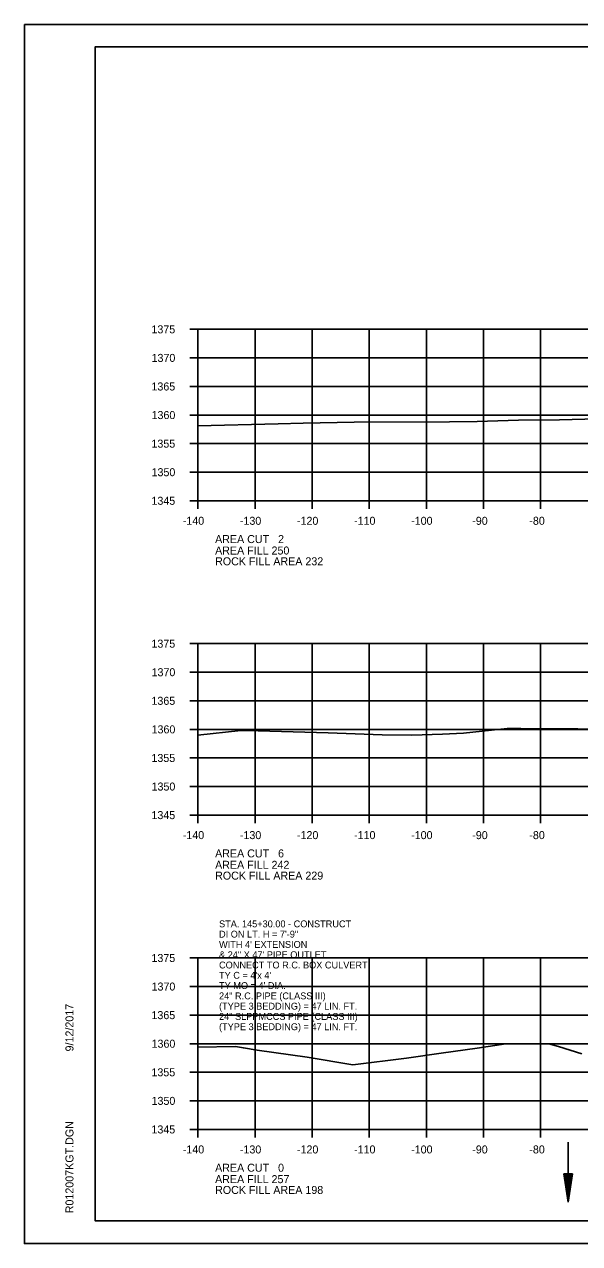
# Model space of a CAD drawing. Extents: x 1374311 to 1383814, y 384102 to 406278.
# Drawn here: x 1381458.2 to 1381555.5, y 390511.4 to 390724.7 of the extents above; entities that cross this region are included whole.
import ezdxf

# ---------------------------------------------------------------- set-up
doc = ezdxf.new("R2010")
doc.units = 0
for name, color, linetype in [('R_Axis', 7, 'Continuous'), ('R_Axis Annot', 7, 'Continuous'), ('R_Border', 7, 'Continuous'), ('R_Draft', 7, 'Continuous'), ('R_Exist Surface', 7, 'Continuous'), ('R_Grid', 7, 'Continuous'), ('R_No Plot', 7, 'Continuous'), ('R_Water', 7, 'Continuous'), ('R_Water Annot', 7, 'Continuous')]:
    doc.layers.add(name, color=color, linetype=linetype)

msp = doc.modelspace()

# ---------------------------------------------------------------- linework, layer by layer
at = {"layer": 'R_Axis'}
for p, q in [((1381487.26, 390671.38), (1381488.66, 390671.38)), ((1381488.66, 390641.38), (1381488.66, 390671.38)), ((1381487.26, 390666.38), (1381488.66, 390666.38)), ((1381487.26, 390661.38), (1381488.66, 390661.38)), ((1381487.26, 390656.38), (1381488.66, 390656.38)), ((1381487.26, 390651.38), (1381488.66, 390651.38)), ((1381487.26, 390646.38), (1381488.66, 390646.38)), ((1381487.26, 390641.38), (1381488.66, 390641.38)), ((1381488.66, 390641.38), (1381768.66, 390641.38)), ((1381488.66, 390639.98), (1381488.66, 390641.38)), ((1381498.66, 390639.98), (1381498.66, 390641.38)), ((1381508.66, 390639.98), (1381508.66, 390641.38)), ((1381518.66, 390639.98), (1381518.66, 390641.38)), ((1381528.66, 390639.98), (1381528.66, 390641.38)), ((1381538.66, 390639.98), (1381538.66, 390641.38)), ((1381548.66, 390639.98), (1381548.66, 390641.38)), ((1381487.26, 390616.38), (1381488.66, 390616.38)), ((1381488.66, 390586.38), (1381488.66, 390616.38)), ((1381487.26, 390611.38), (1381488.66, 390611.38)), ((1381487.26, 390606.38), (1381488.66, 390606.38)), ((1381487.26, 390601.38), (1381488.66, 390601.38)), ((1381487.26, 390596.38), (1381488.66, 390596.38)), ((1381487.26, 390591.38), (1381488.66, 390591.38)), ((1381487.26, 390586.38), (1381488.66, 390586.38)), ((1381488.66, 390586.38), (1381768.66, 390586.38)), ((1381488.66, 390584.98), (1381488.66, 390586.38)), ((1381498.66, 390584.98), (1381498.66, 390586.38)), ((1381508.66, 390584.98), (1381508.66, 390586.38)), ((1381518.66, 390584.98), (1381518.66, 390586.38)), ((1381528.66, 390584.98), (1381528.66, 390586.38)), ((1381538.66, 390584.98), (1381538.66, 390586.38)), ((1381548.66, 390584.98), (1381548.66, 390586.38)), ((1381487.26, 390561.38), (1381488.66, 390561.38)), ((1381488.66, 390531.38), (1381488.66, 390561.38)), ((1381487.26, 390556.38), (1381488.66, 390556.38)), ((1381487.26, 390551.38), (1381488.66, 390551.38)), ((1381487.26, 390546.38), (1381488.66, 390546.38)), ((1381487.26, 390541.38), (1381488.66, 390541.38)), ((1381487.26, 390536.38), (1381488.66, 390536.38)), ((1381487.26, 390531.38), (1381488.66, 390531.38)), ((1381488.66, 390531.38), (1381768.66, 390531.38)), ((1381488.66, 390529.98), (1381488.66, 390531.38)), ((1381498.66, 390529.98), (1381498.66, 390531.38)), ((1381508.66, 390529.98), (1381508.66, 390531.38)), ((1381518.66, 390529.98), (1381518.66, 390531.38)), ((1381528.66, 390529.98), (1381528.66, 390531.38)), ((1381538.66, 390529.98), (1381538.66, 390531.38)), ((1381548.66, 390529.98), (1381548.66, 390531.38))]:
    msp.add_line(p, q, dxfattribs=at)
at = {"layer": 'R_Border'}
for p, q in [((1381470.66, 390720.84), (1381786.84, 390720.84)), ((1381470.66, 390515.38), (1381470.66, 390720.84)), ((1381470.66, 390515.38), (1381470.66, 390515.38)), ((1381786.84, 390515.38), (1381470.66, 390515.38))]:
    msp.add_line(p, q, dxfattribs=at)
at = {"layer": 'R_Draft'}
for p, q in [((1381552.74, 390523.63), (1381553.49, 390518.63)), ((1381554.24, 390523.63), (1381552.74, 390523.63)), ((1381552.87, 390523.63), (1381553.49, 390519.46)), ((1381552.99, 390523.63), (1381553.49, 390520.32)), ((1381553.12, 390523.63), (1381553.49, 390521.16)), ((1381553.25, 390523.63), (1381553.49, 390522)), ((1381553.37, 390523.63), (1381553.49, 390522.84)), ((1381554.24, 390523.63), (1381553.49, 390518.63)), ((1381553.73, 390523.63), (1381553.49, 390522)), ((1381553.99, 390523.63), (1381553.49, 390520.32)), ((1381554.12, 390523.63), (1381553.49, 390519.46)), ((1381553.86, 390523.63), (1381553.49, 390521.16)), ((1381553.61, 390523.63), (1381553.49, 390522.84))]:
    msp.add_line(p, q, dxfattribs=at)
at = {"layer": 'R_Exist Surface'}
for points in [[(1381488.66, 390654.51), (1381502.71, 390654.87), (1381507.06, 390654.97), (1381516.04, 390655.11), (1381532.71, 390655.2), (1381537.54, 390655.26), (1381544.82, 390655.48), (1381552.01, 390655.57), (1381563.05, 390655.85)], [(1381488.66, 390600.35), (1381496.16, 390601.18), (1381496.76, 390601.17), (1381497.17, 390601.16), (1381511.45, 390600.79), (1381520.94, 390600.45), (1381526.11, 390600.38), (1381531.46, 390600.54), (1381535.16, 390600.72), (1381541.71, 390601.42), (1381542.79, 390601.53), (1381543, 390601.53), (1381543.22, 390601.53), (1381545.2, 390601.53), (1381565.23, 390601.44)], [(1381488.66, 390545.75), (1381495.22, 390545.88), (1381496.63, 390545.64), (1381499.05, 390545.27), (1381507.77, 390544.02), (1381515.76, 390542.71), (1381525.17, 390543.84), (1381531.26, 390544.71), (1381537.58, 390545.61), (1381542.57, 390546.33), (1381550.11, 390546.37), (1381551.78, 390545.92), (1381555.87, 390544.61)]]:
    msp.add_lwpolyline(points, dxfattribs=at)
at = {"layer": 'R_Grid'}
for p, q in [((1381488.66, 390671.38), (1381768.66, 390671.38)), ((1381488.66, 390641.38), (1381488.66, 390671.38)), ((1381498.66, 390641.38), (1381498.66, 390671.38)), ((1381508.66, 390641.38), (1381508.66, 390671.38)), ((1381518.66, 390641.38), (1381518.66, 390671.38)), ((1381528.66, 390641.38), (1381528.66, 390671.38)), ((1381538.66, 390641.38), (1381538.66, 390671.38)), ((1381548.66, 390641.38), (1381548.66, 390671.38)), ((1381488.66, 390666.38), (1381768.66, 390666.38)), ((1381488.66, 390661.38), (1381768.66, 390661.38)), ((1381488.66, 390656.38), (1381768.66, 390656.38)), ((1381488.66, 390651.38), (1381768.66, 390651.38)), ((1381488.66, 390646.38), (1381768.66, 390646.38)), ((1381488.66, 390641.38), (1381768.66, 390641.38)), ((1381488.66, 390616.38), (1381768.66, 390616.38)), ((1381488.66, 390586.38), (1381488.66, 390616.38)), ((1381498.66, 390586.38), (1381498.66, 390616.38)), ((1381508.66, 390586.38), (1381508.66, 390616.38)), ((1381518.66, 390586.38), (1381518.66, 390616.38)), ((1381528.66, 390586.38), (1381528.66, 390616.38)), ((1381538.66, 390586.38), (1381538.66, 390616.38)), ((1381548.66, 390586.38), (1381548.66, 390616.38)), ((1381488.66, 390611.38), (1381768.66, 390611.38)), ((1381488.66, 390606.38), (1381768.66, 390606.38)), ((1381488.66, 390601.38), (1381768.66, 390601.38)), ((1381488.66, 390596.38), (1381768.66, 390596.38)), ((1381488.66, 390591.38), (1381768.66, 390591.38)), ((1381488.66, 390586.38), (1381768.66, 390586.38)), ((1381488.66, 390561.38), (1381768.66, 390561.38)), ((1381488.66, 390531.38), (1381488.66, 390561.38)), ((1381498.66, 390531.38), (1381498.66, 390561.38)), ((1381508.66, 390531.38), (1381508.66, 390561.38)), ((1381518.66, 390531.38), (1381518.66, 390561.38)), ((1381528.66, 390531.38), (1381528.66, 390561.38)), ((1381538.66, 390531.38), (1381538.66, 390561.38)), ((1381548.66, 390531.38), (1381548.66, 390561.38)), ((1381488.66, 390556.38), (1381768.66, 390556.38)), ((1381488.66, 390551.38), (1381768.66, 390551.38)), ((1381488.66, 390546.38), (1381768.66, 390546.38)), ((1381488.66, 390541.38), (1381768.66, 390541.38)), ((1381488.66, 390536.38), (1381768.66, 390536.38)), ((1381488.66, 390531.38), (1381768.66, 390531.38))]:
    msp.add_line(p, q, dxfattribs=at)
at = {"layer": 'R_No Plot'}
for p, q in [((1381458.26, 390724.74), (1381791.59, 390724.74)), ((1381458.26, 390511.41), (1381791.59, 390511.41))]:
    msp.add_line(p, q, dxfattribs=at)
for points in [[(1381458.25, 390724.74), (1381791.59, 390724.74), (1381791.59, 390511.4), (1381458.25, 390511.4)], [(1381704.58, 390720.84), (1381704.58, 390710.96), (1381740.31, 390710.96), (1381740.31, 390708.04), (1381763.51, 390708.04), (1381763.51, 390684.83), (1381786.84, 390684.83), (1381786.84, 390515.38), (1381470.66, 390515.38), (1381470.66, 390720.84)]]:
    msp.add_lwpolyline(points, close=True, dxfattribs=at)
at = {"layer": 'R_Water'}
msp.add_line((1381553.49, 390529.13), (1381553.49, 390518.63), dxfattribs=at)

# ---------------------------------------------------------------- texts
at = {"layer": 'R_Axis Annot'}
for s, p in [('1375', (1381480.51, 390670.68)), ('1370', (1381480.53, 390665.68)), ('1365', (1381480.51, 390660.68)), ('1360', (1381480.53, 390655.68)), ('1355', (1381480.51, 390650.68)), ('1350', (1381480.53, 390645.68)), ('1345', (1381480.51, 390640.68)), ('-140', (1381486, 390637.18)), ('-130', (1381496, 390637.18)), ('-120', (1381506, 390637.18)), ('-110', (1381516, 390637.18)), ('-100', (1381526, 390637.18)), ('-90', (1381536.7, 390637.18)), ('-80', (1381546.7, 390637.18)), ('AREA CUT   2', (1381491.66, 390633.98)), ('AREA FILL 250', (1381491.66, 390631.98)), ('ROCK FILL AREA 232', (1381491.66, 390630.09)), ('1375', (1381480.51, 390615.68)), ('1370', (1381480.53, 390610.68)), ('1365', (1381480.51, 390605.68)), ('1360', (1381480.53, 390600.68)), ('1355', (1381480.51, 390595.68)), ('1350', (1381480.53, 390590.68)), ('1345', (1381480.51, 390585.68)), ('-140', (1381486, 390582.18)), ('-130', (1381496, 390582.18)), ('-120', (1381506, 390582.18)), ('-110', (1381516, 390582.18)), ('-100', (1381526, 390582.18)), ('-90', (1381536.7, 390582.18)), ('-80', (1381546.7, 390582.18)), ('AREA CUT   6', (1381491.66, 390578.98)), ('AREA FILL 242', (1381491.66, 390576.98)), ('ROCK FILL AREA 229', (1381491.66, 390575.09)), ('1375', (1381480.51, 390560.68)), ('1370', (1381480.53, 390555.68)), ('1365', (1381480.51, 390550.68)), ('1360', (1381480.53, 390545.68)), ('1355', (1381480.51, 390540.68)), ('1350', (1381480.53, 390535.68)), ('1345', (1381480.51, 390530.68)), ('-140', (1381486, 390527.18)), ('-130', (1381496, 390527.18)), ('-120', (1381506, 390527.18)), ('-110', (1381516, 390527.18)), ('-100', (1381526, 390527.18)), ('-90', (1381536.7, 390527.18)), ('-80', (1381546.7, 390527.18)), ('AREA CUT   0', (1381491.66, 390523.98)), ('AREA FILL 257', (1381491.66, 390521.98)), ('ROCK FILL AREA 198', (1381491.66, 390520.09))]:
    msp.add_text(s, height=1.4, dxfattribs=at).set_placement(p)
at = {"layer": 'R_Border'}
for s, p in [('9/12/2017', (1381466.85, 390545.03)), ('R012007KGT.DGN', (1381466.85, 390516.71))]:
    msp.add_text(s, height=1.4, rotation=90, dxfattribs=at).set_placement(p)
at = {"layer": 'R_Water Annot'}
for s, p in [('STA. 145+30.00 - CONSTRUCT', (1381492.35, 390566.75)), ('DI ON LT. H = 7\'-9"', (1381492.35, 390564.95)), ("WITH 4' EXTENSION ", (1381492.35, 390563.15)), ('& 24" X 47\' PIPE OUTLET', (1381492.35, 390561.35)), ('CONNECT TO R.C. BOX CULVERT', (1381492.35, 390559.55)), ("TY C = 4'x 4'", (1381492.35, 390557.75)), ("TY MO = 4' DIA.", (1381492.35, 390555.95)), ('24" R.C. PIPE (CLASS III)', (1381492.35, 390554.15)), ('(TYPE 3 BEDDING) = 47 LIN. FT.', (1381492.35, 390552.35)), ('24" SLPPMCCS PIPE (CLASS III)', (1381492.35, 390550.55)), ('(TYPE 3 BEDDING) = 47 LIN. FT.', (1381492.35, 390548.75))]:
    msp.add_text(s, height=1.2, dxfattribs=at).set_placement(p)

doc.saveas('drawing.dxf')
